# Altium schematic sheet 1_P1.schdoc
size 307 x 218 mm; Symbol: Drawing-Symbol_A4; Device: Drawing-Symbol_A4; Company: 嘉立创EDA; Version: V1.0; Page Size: A4; @Project Name: ESP32_C3_RX; @Page Count: 1; @Update Date: 2025-06-15; @Create Date: 2025-06-14; @Schematic Name: Schematic1; @Page No: 1; @Page Name: P1; @Create Time: 20:50:11; @Update Time: 09:58:54; Width: 1170; Height: 825; Region Start: 1; X Region Count: 6; Y Region Count: 4; Blade Width: 10; Title Block Position: 3; @Board Name: Board1
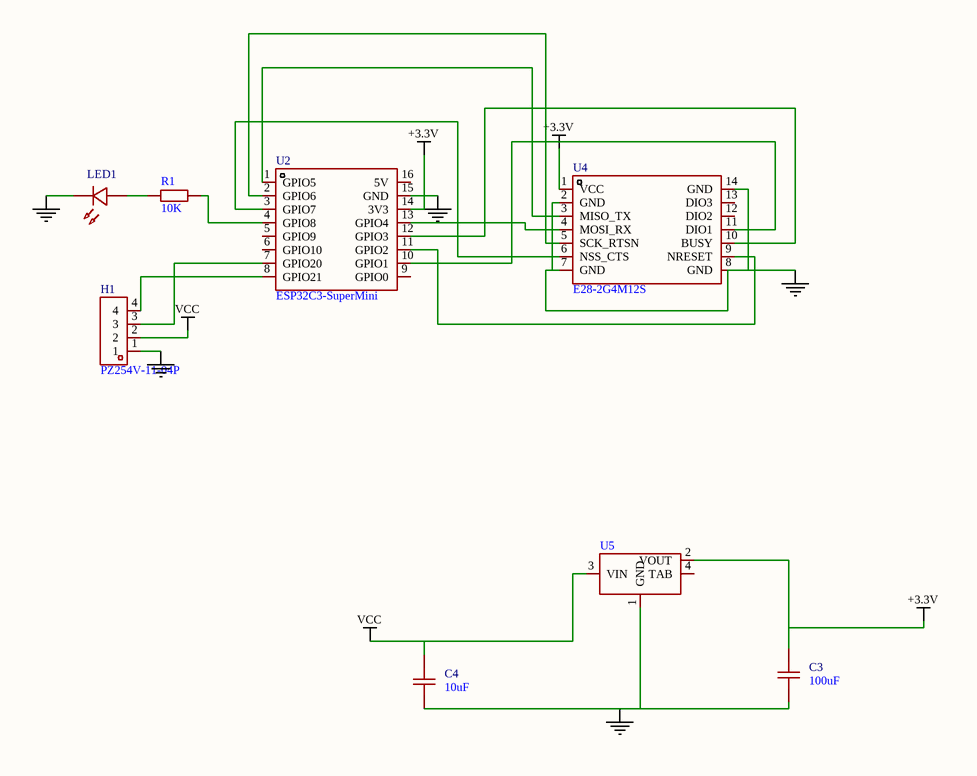
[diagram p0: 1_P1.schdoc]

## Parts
C3  100uF  [C1206]
C4  10uF  [C1206]
H1  PZ254V-11-04P  [HDR-TH_4P-P2.54-V-M]
LED1  (no value)  [LED_0603]
R1  10K  [R0603]
U2  ESP32C3-SuperMini  [COMM-SMD_16P-L22.5-W18.0-P2.54-TL]
U4  E28-2G4M12S  [WIRELM-SMD_E28-2G4M12S]
U5  (no value)  [SOT_223]

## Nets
+3.3V: C3.2 U2.14(3V3) U4.1(VCC) U5.2(VOUT)
GND: C3.1 C4.1 H1.1 LED1.1(C) U2.15(GND) U4.2(GND) U4.7(GND) U4.8(GND) U4.14(GND) U5.1(GND)
VCC: C4.2 H1.2 U5.3(VIN)
NetH1_3: H1.3 U2.7(GPIO20)
NetH1_4: H1.4 U2.8(GPIO21)
NetLED1_2: LED1.2(A) R1.1
NetR1_2: R1.2 U2.4(GPIO8)
NetU2_1: U2.1(GPIO5) U4.3(MISO_TX)
NetU2_2: U2.2(GPIO6) U4.5(SCK_RTSN)
NetU2_3: U2.3(GPIO7) U4.6(NSS_CTS)
NetU2_10: U2.10(GPIO1) U4.11(DIO1)
NetU2_11: U2.11(GPIO2) U4.9(NRESET)
NetU2_12: U2.12(GPIO3) U4.10(BUSY)
NetU2_13: U2.13(GPIO4) U4.4(MOSI_RX)

Not connected (* = marked no-connect by the designer): U2 5(GPIO9) 6(GPIO10) 9(GPIO0) 16(5V); U4 12(DIO2) 13(DIO3); U5 4(TAB)

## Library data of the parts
C3 C4 = GRM31CR61A107MEA8L: Manufacturer: muRata(村田); Add into BOM: yes; Tolerance: ±20%; Voltage Rated: 10V; Temperature Coefficient: X5R
H1 = PZ254V-11-04P: Manufacturer: XFCN(兴飞); Symbol: PZ254V-11-04P_C2691448; Add into BOM: yes; Pin Structure: 1x4P; Pitch: 2.54mm; Circluar Pins/Square Pins: 方针; Current Rating (Max): 3A; Voltage Rating (Max): 250V
LED1 = LED_0603-R: Symbol: LED_R; Convert to PCB: yes
R1 = Res_0603: Symbol: 电阻; Convert to PCB: yes
U2 = ESP32C3-SuperMini: Add into BOM: yes
U4 = E28-2G4M12S: Manufacturer: EBYTE(亿佰特); Add into BOM: yes; Output Power: 12.5dBm; Interface Type: SPI; Modulation System: LoRa；FLRC；GFSK; Voltage - Supply: 1.8V~3.6V; Antenna Type: IPEX接口；板载PCB天线; Receive  Current: 10mA; Send  Current: 45mA; Sensitivity: -129dBm; Communication Distance: 3km
U5 = AMS1117: Symbol: AMS1117_OLD; Add into BOM: yes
